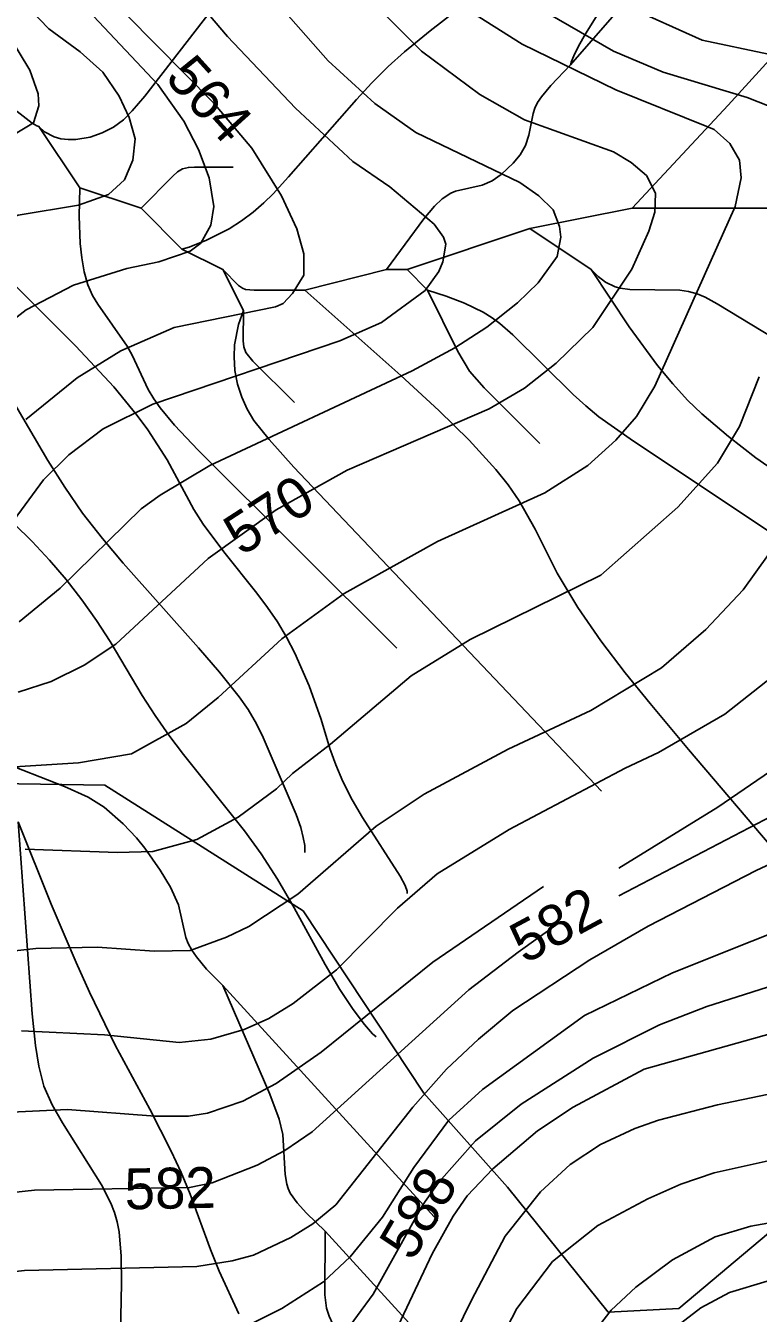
# Model space of a CAD drawing. Extents: x -709584 to -702006, y -1161789 to -1157496.
# Drawn here: x -709080.2 to -708901.1, y -1161487.1 to -1161172.4 of the extents above; entities that cross this region are included whole.
import ezdxf

# ---------------------------------------------------------------- set-up
doc = ezdxf.new("R2010")
doc.units = 0
for name, color, linetype in [('103_hranice KÚ', 7, 'Continuous'), ('120_vrstevnice hlavní', 7, 'Continuous'), ('121_vrstevnice hlavní_popis', 7, 'Continuous'), ('122_vrstevnice základní', 7, 'Continuous'), ('411_akumulovaný odtok', 7, 'Continuous')]:
    doc.layers.add(name, color=color, linetype=linetype)

msp = doc.modelspace()

# ---------------------------------------------------------------- linework, layer by layer
at = {"layer": '103_hranice KÚ'}
msp.add_lwpolyline([(-709234.65, -1161164.22), (-709251.02, -1161179.72), (-709249.63, -1161198), (-709213.45, -1161287.54), (-709205.25, -1161308.17), (-709193.08, -1161348.59), (-709153.37, -1161348.24), (-709123.88, -1161357.03), (-709060.82, -1161357.99), (-709012.33, -1161388.76), (-708982.87, -1161433.3), (-708962.39, -1161456.22), (-708937.82, -1161486.79), (-708920.55, -1161485.93), (-708896.6, -1161465.8)], dxfattribs=at)
at = {"layer": '120_vrstevnice hlavní'}
for points in [[(-709079.02, -1161168.53), (-709074.53, -1161173.16), (-709066.87, -1161178.8), (-709061.37, -1161183.72), (-709057.32, -1161189.65), (-709054.86, -1161194.85), (-709053.42, -1161200.06), (-709054, -1161205.27), (-709056.02, -1161210.04), (-709059.93, -1161213.66)], [(-708995.85, -1161166.21), (-708983.41, -1161178.65), (-708969.23, -1161189.21), (-708958.24, -1161195.43), (-708936.54, -1161203.24), (-708932.21, -1161205.84), (-708928.44, -1161209.03)], [(-708935.18, -1161378.26), (-708911.01, -1161363.35), (-708896.62, -1161353.53), (-708886.93, -1161345.57), (-708881, -1161339.21), (-708877.38, -1161334.43), (-708871.6, -1161323.59), (-708868.56, -1161315.49), (-708857.86, -1161273.54), (-708852.22, -1161258.79), (-708842.09, -1161239.11), (-708806.8, -1161180.1), (-708804.34, -1161173.73), (-708804.34, -1161170.26)], [(-708928.44, -1161209.03), (-708926.27, -1161213.37), (-708926.42, -1161218), (-708927.87, -1161222.62), (-708932.06, -1161231.88), (-708941.61, -1161246.2), (-708950.57, -1161254.88), (-708958.24, -1161260.96), (-708966.92, -1161266.02), (-709001.63, -1161281.06), (-709018.99, -1161290.75), (-709035.62, -1161302.61), (-709058.19, -1161323.59), (-709065.86, -1161328.65), (-709073.96, -1161332.7), (-709082.06, -1161335.3)], [(-709059.93, -1161213.66), (-709067.3, -1161216.26), (-709082.06, -1161218.72), (-709091.89, -1161222.48), (-709101.73, -1161228.55), (-709114.75, -1161240.56), (-709134.95, -1161267.22), (-709141, -1161271.45), (-709148.82, -1161275.61), (-709161.92, -1161277.32), (-709170.87, -1161279.18), (-709178.97, -1161282.22), (-709195.17, -1161290.46), (-709215.42, -1161296.68), (-709223.81, -1161292.05), (-709240.01, -1161287.14), (-709252.16, -1161285.4), (-709260.26, -1161285.11), (-709268.36, -1161285.69), (-709280.51, -1161287.86), (-709332.87, -1161304.06), (-709361.7, -1161310.62)], [(-709194.3, -1161457.09), (-709181.57, -1161463.02), (-709170.29, -1161466.21), (-709162.77, -1161467.07), (-709154.96, -1161466.93), (-709149.17, -1161466.06), (-709143.1, -1161462.73), (-709122.85, -1161447.55), (-709114.75, -1161443.06), (-709106.07, -1161440.03), (-709097.39, -1161438.58), (-709069.98, -1161437.27), (-709048.5, -1161438.87), (-709040.4, -1161438.87), (-709035.77, -1161438.14), (-709027.09, -1161435.25), (-709018.99, -1161430.91), (-709008, -1161423.25), (-708980.66, -1161401.26), (-708953.61, -1161382.78)], [(-708859.59, -1161407.91), (-708929.02, -1161427.44), (-708946.38, -1161436.7), (-708955.06, -1161442.48), (-708966.05, -1161451.74), (-708972.27, -1161458.39), (-708975.74, -1161463.31), (-708980.81, -1161472.57), (-708993.97, -1161500.34), (-708999.18, -1161509.6), (-709005.39, -1161518.57), (-709013.93, -1161527.53), (-709018.99, -1161531.58), (-709027.67, -1161535.49)]]:
    msp.add_lwpolyline(points, dxfattribs=at)
at = {"layer": '122_vrstevnice základní'}
for points in [[(-708697.59, -1161129.04), (-708733.32, -1161184.73), (-708743.59, -1161203.24), (-708750.96, -1161219.44), (-708758.78, -1161242.58), (-708764.27, -1161270.36), (-708767.89, -1161300.44), (-708768.03, -1161318.96), (-708767.17, -1161344.42), (-708767.45, -1161355.99), (-708769.19, -1161367.56), (-708771.5, -1161376.81), (-708775.84, -1161388.39), (-708781.92, -1161399.96), (-708786.98, -1161407.05), (-708793.2, -1161413.84), (-708802.75, -1161422.09), (-708812.73, -1161428.02), (-708839.05, -1161438.29), (-708853.23, -1161442.92), (-708867.4, -1161445.38), (-708895.75, -1161449.14), (-708911.95, -1161452.75), (-708920.06, -1161455.5)], [(-709036.06, -1161147.12), (-709006.26, -1161180.97)], [(-708759.21, -1161151.75), (-708797.11, -1161207.29), (-708816.06, -1161239.69), (-708824.01, -1161255.89), (-708832.26, -1161276.72), (-708849.32, -1161332.27), (-708852.65, -1161339.21), (-708858.29, -1161348.47), (-708863.64, -1161355.41), (-708869.57, -1161361.34), (-708878.11, -1161367.85), (-708901.69, -1161378.84), (-708928.01, -1161392.44), (-708942.33, -1161400.68), (-708961.13, -1161413.12), (-708969.52, -1161420.06), (-708977.33, -1161427.44), (-708985.58, -1161436.7)], [(-709034.9, -1161221.18), (-709034.18, -1161216.55), (-709035.34, -1161209.61), (-709037.94, -1161202.66), (-709041.56, -1161195.72), (-709047.92, -1161186.75), (-709078.01, -1161154.64)], [(-709061.23, -1161270.94), (-709049.08, -1161264.86), (-709003.37, -1161249.38), (-708993.25, -1161244.9), (-708982.54, -1161237.09), (-708979.21, -1161232.46), (-708978.2, -1161230.15), (-708977.48, -1161225.81), (-708978.06, -1161224.07), (-708980.37, -1161220.89), (-708991.22, -1161211.78), (-709000.19, -1161205.56), (-709014.22, -1161192.54), (-709030.85, -1161175.04), (-709046.18, -1161156.96)], [(-708935.18, -1161385.03), (-708897.78, -1161365.53), (-708888.52, -1161360.04), (-708879.84, -1161353.38), (-708871.74, -1161344.13), (-708863.93, -1161331.11), (-708855.69, -1161307.68), (-708851.06, -1161289.45), (-708841.95, -1161263.41), (-708836.31, -1161250.4), (-708831.1, -1161239.98), (-708815.91, -1161213.95), (-708802.6, -1161193.7), (-708788.28, -1161173.45), (-708779.32, -1161158.98)], [(-709085.53, -1161353.67), (-709067.3, -1161352.52), (-709054.29, -1161350.34), (-709040.98, -1161342.97), (-709033.17, -1161336.6), (-709017.55, -1161322.28), (-709002.36, -1161311.15), (-708979.56, -1161298.5), (-708953.32, -1161286.56), (-708942.76, -1161279.9), (-708935.96, -1161273.68), (-708930.9, -1161267.9), (-708926.42, -1161260.52), (-708906.75, -1161216.55), (-708905.3, -1161209.61), (-708905.73, -1161205.27), (-708908.05, -1161201.22), (-708911.9, -1161197.74), (-708913.69, -1161197.02), (-708935.96, -1161188.05), (-708958.82, -1161176.92), (-708979.36, -1161163.9)], [(-708955.35, -1161167.8), (-708936.54, -1161178.65), (-708924.39, -1161183.72)], [(-708898.65, -1161179.38), (-708914.85, -1161175.9), (-708933.36, -1161167.66)], [(-709055.44, -1161169.83), (-709034.32, -1161191.24), (-709024.92, -1161202.37), (-709017.69, -1161213.95), (-709013.93, -1161222.05), (-709012.19, -1161228.12), (-709012.19, -1161233.33), (-709014.94, -1161237.81), (-709017.26, -1161240.27), (-709019.14, -1161241.14), (-709043.87, -1161246.2), (-709056.89, -1161251.84), (-709067.59, -1161258.5), (-709080.18, -1161268.62)], [(-709084.37, -1161174.6), (-709079.16, -1161183.28), (-709077.14, -1161189.07), (-709076.99, -1161191.96), (-709078.3, -1161196.15), (-709087.55, -1161201.65)], [(-709006.26, -1161180.97), (-708994.83, -1161191.38), (-708984.85, -1161198.47), (-708959.4, -1161210.76), (-708954.77, -1161213.95), (-708951.3, -1161217.42), (-708949.71, -1161221.47), (-708949.42, -1161224.07), (-708950.29, -1161228.84), (-708954.91, -1161235.21), (-708959.98, -1161240.13), (-708967.5, -1161246.06), (-708975.31, -1161251.12), (-708985.72, -1161256.76), (-709035.19, -1161279.9), (-709047.34, -1161287.14), (-709051.97, -1161290.46), (-709071.79, -1161309.84), (-709081.77, -1161318.09)], [(-708924.39, -1161183.72), (-708903.85, -1161189.94), (-708895.75, -1161193.12)], [(-709257.08, -1161299), (-709243.77, -1161299.86), (-709237.69, -1161300.88), (-709229.59, -1161303.34), (-709215.42, -1161309.41), (-709210.07, -1161314.33), (-709207.61, -1161315.78), (-709205.58, -1161315.78), (-709198.35, -1161313.17), (-709193.14, -1161312.02), (-709168.55, -1161300.3), (-709139.91, -1161291.04), (-709127.33, -1161285.54), (-709116.48, -1161278.02), (-709097.53, -1161256.91), (-709090.88, -1161250.25), (-709080.03, -1161241.86), (-709068.46, -1161235.79), (-709055.44, -1161231.74), (-709047.63, -1161230.15), (-709039.96, -1161227.54), (-709037.36, -1161225.52), (-709034.9, -1161221.18)], [(-708900.96, -1161258.21), (-708905.73, -1161270.36), (-708911.09, -1161279.32), (-708920.78, -1161290.03), (-708939.58, -1161306.66), (-708971.55, -1161322.43), (-708986.01, -1161331.25), (-709005.68, -1161348.03), (-709014.94, -1161355.12), (-709018.85, -1161358.88), (-709028.25, -1161365.82), (-709038.37, -1161371.32), (-709049.08, -1161374.21), (-709057.76, -1161374.5), (-709080.32, -1161373.63)], [(-709256.79, -1161323.88), (-709246.66, -1161327.35), (-709236.54, -1161332.27), (-709230.46, -1161335.88), (-709221.35, -1161342.97), (-709210.5, -1161350.06), (-709203.27, -1161352.37), (-709197.19, -1161352.8), (-709189.96, -1161351.36), (-709185.75, -1161349.38), (-709184.32, -1161347.45), (-709179.98, -1161342.39), (-709171.3, -1161335.45), (-709164.5, -1161331.98), (-709131.23, -1161320.11), (-709102.6, -1161311.15), (-709093.48, -1161305.36), (-709087.84, -1161299.57), (-709075.84, -1161283.38), (-709069.62, -1161277.3), (-709061.23, -1161270.94)], [(-709087.26, -1161398.95), (-709077.72, -1161397.93), (-709062.67, -1161397.64), (-709048.81, -1161398.62), (-709039.99, -1161398.38), (-709031.14, -1161395.19), (-709025.65, -1161392.58), (-709013.64, -1161384.63), (-708994.55, -1161367.99), (-708982.83, -1161360.18), (-708962.29, -1161349.19), (-708942.04, -1161339.79), (-708924.83, -1161329.37), (-708913.98, -1161319.97), (-708904.87, -1161310.28), (-708898.65, -1161301.6)], [(-708896.62, -1161330.67), (-708909.35, -1161340.65), (-708925.55, -1161350.06), (-708933.65, -1161353.82), (-708962, -1161368.86), (-708979.65, -1161379.71), (-708989.34, -1161388.1), (-709004.24, -1161403.14), (-709014.8, -1161411.39), (-709020.73, -1161415), (-709026.8, -1161417.75), (-709034.9, -1161420.06), (-709042.71, -1161420.93), (-709060.94, -1161419.05), (-709081.19, -1161418.04)], [(-708883.32, -1161388.39), (-708922.08, -1161403.86), (-708943.63, -1161414.28), (-708968.51, -1161432.36), (-708976.76, -1161439.88), (-708985.29, -1161451.45), (-708992.96, -1161463.6), (-709000.91, -1161473.29), (-709007.42, -1161479.37), (-709017.55, -1161485.88), (-709025.93, -1161490.07), (-709040.69, -1161495.28), (-709050.23, -1161497.16), (-709062.09, -1161498.17)], [(-709176.94, -1161480.81), (-709162.77, -1161481.97), (-709151.49, -1161483.56), (-709146.86, -1161482.12), (-709130.66, -1161473.87), (-709117.06, -1161466.21), (-709101.44, -1161460.56), (-709091.02, -1161458.4), (-709078.01, -1161456.95), (-709040.11, -1161456.37), (-709034.61, -1161455.21), (-709023.62, -1161450.87), (-709016.82, -1161447.26), (-709010.17, -1161442.77), (-708971.84, -1161408.06), (-708959.83, -1161398.8), (-708949.47, -1161391.43)], [(-708876.66, -1161400.25), (-708913.69, -1161412.11), (-708925.26, -1161416.59), (-708941.46, -1161424.69), (-708959.11, -1161435.97), (-708970.25, -1161444.94), (-708979.21, -1161455.07), (-708983.12, -1161460.56), (-708995.27, -1161482.41), (-709002.94, -1161492.82), (-709007.56, -1161498.17), (-709013.21, -1161503.52), (-709020.73, -1161509.02)], [(-708989.05, -1161520.3), (-708971.26, -1161483.85), (-708963.01, -1161468.23), (-708954.33, -1161457.38), (-708947.1, -1161450.73), (-708939.73, -1161445.81), (-708931.34, -1161441.91), (-708925.55, -1161439.88), (-708911.09, -1161436.12), (-708888.81, -1161431.49)], [(-708985.58, -1161436.7), (-709004.38, -1161460.56), (-709010.02, -1161465.19), (-709015.38, -1161468.52), (-709024.49, -1161472.86), (-709029.7, -1161474.3), (-709038.37, -1161475.61), (-709080.46, -1161476.65), (-709093.82, -1161478.11), (-709107.04, -1161481.47), (-709117.35, -1161485.73), (-709138.9, -1161498.17), (-709148.59, -1161504.82), (-709156.4, -1161504.82), (-709179.84, -1161499.76), (-709192.85, -1161494.56), (-709198.06, -1161491.52), (-709210.5, -1161482.55), (-709219.32, -1161474.88), (-709251.58, -1161442.63), (-709258.52, -1161437.57)], [(-708920.06, -1161455.5), (-708928.16, -1161459.12), (-708940.31, -1161465.63), (-708951.44, -1161474.45), (-708960.12, -1161485.88), (-708963.74, -1161492.82)], [(-708945.95, -1161497.74), (-708937.12, -1161486.31), (-708931.05, -1161480.67), (-708922.08, -1161474.02), (-708911.67, -1161468.38), (-708902.99, -1161465.77), (-708891.42, -1161463.75)], [(-708898.94, -1161479.22), (-708908.19, -1161481.97), (-708915.14, -1161485.73), (-708924.07, -1161492.56)]]:
    msp.add_lwpolyline(points, dxfattribs=at)
at = {"layer": '411_akumulovaný odtok'}
for p, q in [((-709066.99, -1161212), (-709076.99, -1161197)), ((-709051.99, -1161217), (-709066.99, -1161212)), ((-709041.99, -1161227), (-709051.99, -1161217)), ((-708931.99, -1161217), (-708956.99, -1161222)), ((-708891.99, -1161217), (-708931.99, -1161217)), ((-708956.99, -1161222), (-708986.99, -1161232)), ((-708941.99, -1161232), (-708956.99, -1161222)), ((-709031.99, -1161232), (-709041.99, -1161227)), ((-709026.99, -1161242), (-709031.99, -1161232)), ((-708991.99, -1161232), (-709011.99, -1161237)), ((-708986.99, -1161232), (-708991.99, -1161232)), ((-708981.99, -1161237), (-708986.99, -1161232)), ((-708979.49, -1161464.5), (-709031.99, -1161407))]:
    msp.add_line(p, q, dxfattribs=at)
for points in [[(-708859.49, -1161049.5), (-708865.18, -1161058.29), (-708869.11, -1161064.76), (-708872.83, -1161071.51), (-708874.36, -1161074.69), (-708875.54, -1161077.59), (-708876.46, -1161080.43), (-708877.95, -1161086.24), (-708879.95, -1161095.03), (-708881.5, -1161100.77), (-708882.45, -1161103.56), (-708883.59, -1161106.26), (-708885.04, -1161108.98), (-708886.69, -1161111.61), (-708890.39, -1161116.68), (-708896.46, -1161124.04), (-708946.99, -1161182)], [(-708939.49, -1161134.5), (-708941.17, -1161137.34), (-708943.97, -1161141.34), (-708948.07, -1161146.25), (-708950.53, -1161148.81), (-708953.05, -1161151.23), (-708957.75, -1161155.29), (-708981.3, -1161173.64), (-708987.59, -1161178.79), (-708991.62, -1161182.39), (-708995.56, -1161186.33), (-708999.36, -1161190.43), (-709015.96, -1161209.35), (-709019.74, -1161213.49), (-709022.01, -1161215.69), (-709024.62, -1161217.94), (-709027.47, -1161220.11), (-709030.46, -1161222.05), (-709035.98, -1161224.85), (-709040.25, -1161226.5), (-709041.99, -1161227)], [(-709021.99, -1161152), (-709051.1, -1161189.61), (-709054.13, -1161193.22), (-709056.31, -1161195.4), (-709058.76, -1161197.18), (-709061.49, -1161198.55), (-709064.41, -1161199.61), (-709067.95, -1161200.2), (-709069.81, -1161200.22), (-709071.61, -1161200.02), (-709073.25, -1161199.58), (-709075.58, -1161198.34), (-709076.99, -1161197)], [(-709076.99, -1161197), (-709077.48, -1161196.87), (-709078.6, -1161196.19), (-709082.23, -1161193.38), (-709095.41, -1161180.8), (-709098.06, -1161178.67), (-709100.55, -1161177.08), (-709103.08, -1161175.76), (-709108.39, -1161173.49), (-709130.66, -1161165.63)], [(-708940.79, -1161170.25), (-708943.4, -1161174.4), (-708945.08, -1161177.39), (-708946.25, -1161179.76), (-708946.9, -1161181.35), (-708946.99, -1161182)], [(-708887.96, -1161168.93), (-708895.04, -1161177.1), (-708908.53, -1161191.86), (-708931.99, -1161217)], [(-708946.99, -1161182), (-708951.87, -1161186.98), (-708954.15, -1161189.79), (-708955.07, -1161191.2), (-708955.74, -1161192.55), (-708956.15, -1161193.83), (-708957.2, -1161199.14), (-708958, -1161201.68), (-708959.33, -1161203.95), (-708961.04, -1161206.03), (-708964.01, -1161208.8), (-708966.2, -1161210.31), (-708968.62, -1161211.34), (-708975.12, -1161212.84), (-708976.31, -1161213.32), (-708978.41, -1161214.71), (-708980.28, -1161216.51), (-708982.9, -1161219.62), (-708991.99, -1161232)], [(-709029.49, -1161207), (-709038.89, -1161206.94), (-709040.41, -1161207.03), (-709041.84, -1161207.36), (-709043.09, -1161208.14), (-709044.23, -1161209.17), (-709051.99, -1161217)], [(-709011.99, -1161374.5), (-709012, -1161372.72), (-709012.34, -1161370.8), (-709012.96, -1161368.37), (-709014.06, -1161365.16), (-709022.16, -1161346.39), (-709023.81, -1161343), (-709025.85, -1161339.54), (-709028.03, -1161336.43), (-709032.81, -1161330.36), (-709037.92, -1161324.42), (-709056.34, -1161303.76), (-709061.44, -1161297.73), (-709066.29, -1161291.51), (-709070.64, -1161285.18), (-709074.74, -1161278.66), (-709092.35, -1161248.74), (-709098.69, -1161238.6), (-709101.43, -1161234.75), (-709107.49, -1161227.19), (-709113.46, -1161220.58), (-709121.99, -1161212)], [(-708989.49, -1161324.5), (-709037.99, -1161276.17), (-709043.78, -1161270.01), (-709047.31, -1161265.77), (-709048.88, -1161263.57), (-709050.26, -1161261.29), (-709054.13, -1161252.89), (-709055.35, -1161250.74), (-709062.55, -1161240.47), (-709063.86, -1161238.31), (-709064.99, -1161235.72), (-709065.88, -1161232.58), (-709066.49, -1161229.16), (-709066.86, -1161225.63), (-709067.13, -1161218.96), (-709066.99, -1161212)], [(-708986.99, -1161384.5), (-708986.94, -1161383.91), (-708987.47, -1161382.5), (-708988.68, -1161380.23), (-708997.86, -1161365.92), (-709000.4, -1161361.58), (-709002.68, -1161357.14), (-709004.42, -1161353.03), (-709005.83, -1161349.07), (-709007.98, -1161341.99), (-709010.9, -1161333.77), (-709014.43, -1161325.75), (-709016.45, -1161321.87), (-709018.68, -1161318.11), (-709021.1, -1161314.56), (-709023.69, -1161311.11), (-709031.77, -1161301.02), (-709036.83, -1161294.19), (-709039.06, -1161290.65), (-709045.59, -1161278.54), (-709050.31, -1161271.19), (-709052.91, -1161267.63), (-709058.66, -1161260.69), (-709067.96, -1161250.7), (-709084.12, -1161234.51)], [(-709011.99, -1161237), (-709024.36, -1161237.04), (-709026.48, -1161236.84), (-709027.21, -1161236.55), (-709028.18, -1161235.86), (-709031.99, -1161232)], [(-708891.99, -1161252), (-708911.19, -1161240.37), (-708914.12, -1161238.78), (-708916.11, -1161237.9), (-708918.19, -1161237.33), (-708920.34, -1161237.06), (-708932.5, -1161236.89), (-708934.87, -1161236.57), (-708936.15, -1161236.2), (-708938.48, -1161235.05), (-708940.3, -1161233.68), (-708941.99, -1161232)], [(-708894.85, -1161282.78), (-708901.74, -1161278.03), (-708908.45, -1161272.83), (-708914.96, -1161267.24), (-708918.4, -1161263.88), (-708922, -1161259.94), (-708925.74, -1161255.42), (-708932.72, -1161245.99), (-708941.99, -1161232)], [(-708851.99, -1161427), (-708918.21, -1161349.27), (-708927.57, -1161338.09), (-708933.66, -1161330.55), (-708939.59, -1161322.73), (-708945.21, -1161314.6), (-708950.27, -1161306.19), (-708955.69, -1161295.46), (-708959.55, -1161288.52), (-708962.26, -1161284.6), (-708965.24, -1161280.85), (-708971.76, -1161273.69), (-708979.18, -1161266.45), (-708988.49, -1161257.9), (-709011.99, -1161237)], [(-708954.49, -1161274.5), (-708968.14, -1161260.92), (-708971.75, -1161256.84), (-708974.53, -1161252.04), (-708981.99, -1161237)], [(-708896.99, -1161297), (-708931.64, -1161273.97), (-708940.1, -1161267.97), (-708943.3, -1161265.34), (-708946.36, -1161262.54), (-708961.16, -1161247.97), (-708964.27, -1161245.2), (-708966.18, -1161243.8), (-708968.37, -1161242.43), (-708972.97, -1161240.18), (-708977.38, -1161238.48), (-708981.99, -1161237)], [(-708939.49, -1161359.5), (-709014.62, -1161280.26), (-709020.69, -1161273.54), (-709024.42, -1161268.9), (-709026.09, -1161266.12), (-709027.39, -1161263.17), (-709028.39, -1161259.97), (-709029.03, -1161256.66), (-709029.26, -1161253.36), (-709029.11, -1161250.4), (-709028.18, -1161245.39), (-709026.99, -1161242)], [(-709014.49, -1161264.5), (-709024.7, -1161254.37), (-709026.39, -1161252.31), (-709026.9, -1161250.91), (-709027.05, -1161249.4), (-709026.99, -1161242)], [(-708994.49, -1161419.5), (-708995.41, -1161418.8), (-708997.39, -1161416.5), (-709000.14, -1161412.8), (-709003.39, -1161407.92), (-709006.97, -1161401.86), (-709014.56, -1161388), (-709018.63, -1161381), (-709022.67, -1161374.77), (-709026.68, -1161369.2), (-709041.62, -1161350.53), (-709045.19, -1161345.81), (-709048.55, -1161341.02), (-709051.73, -1161336.13), (-709059.52, -1161322.9), (-709062.86, -1161317.73), (-709066.47, -1161312.69), (-709070.32, -1161307.78), (-709074.37, -1161303.02), (-709078.63, -1161298.43), (-709082.98, -1161294.12)], [(-709031.99, -1161407), (-709035.96, -1161403), (-709038.45, -1161399.97), (-709039.56, -1161398.34), (-709040.45, -1161396.7), (-709041.03, -1161395.25), (-709042.86, -1161387.24), (-709044.83, -1161382.91), (-709047.34, -1161378.75), (-709051.1, -1161373.39), (-709053.12, -1161370.91), (-709056.35, -1161367.5), (-709061.01, -1161363.38), (-709064.95, -1161360.91), (-709070.69, -1161358.32), (-709086.99, -1161352)], [(-709056.99, -1161492), (-709056.76, -1161479.69), (-709056.88, -1161473.11), (-709057.37, -1161467.18), (-709057.82, -1161464.76), (-709058.46, -1161462.46), (-709059.35, -1161460.15), (-709061.64, -1161455.69), (-709071.2, -1161440.56), (-709073.69, -1161436.14), (-709075.71, -1161431.57), (-709077.01, -1161426.68), (-709077.82, -1161421.62), (-709078.6, -1161413.88), (-709081.99, -1161367)], [(-709028.1, -1161487.21), (-709032.86, -1161476.77), (-709035.04, -1161471.46), (-709039.96, -1161457.94), (-709042.16, -1161452.69), (-709044.59, -1161447.49), (-709049.88, -1161437.18), (-709058.28, -1161421.58), (-709064.61, -1161408.57), (-709067.85, -1161401.35), (-709073.92, -1161387.09), (-709081.99, -1161367)], [(-709006.99, -1161467), (-709011.57, -1161462.6), (-709013.81, -1161460.12), (-709015.52, -1161457.72), (-709016.02, -1161456.62), (-709016.36, -1161455.52), (-709016.74, -1161453.18), (-709017.36, -1161443.35), (-709018.22, -1161439.64), (-709020.55, -1161433.55), (-709031.99, -1161407)], [(-708986.99, -1161517), (-709002.83, -1161493.4), (-709005.11, -1161489.71), (-709006.05, -1161487.81), (-709006.67, -1161485.8), (-709007.06, -1161482.58), (-709006.99, -1161467)], [(-708924.49, -1161544.5), (-708930.27, -1161538.92), (-708934.63, -1161535.33), (-708936.96, -1161533.69), (-708941.55, -1161531.07), (-708949.51, -1161527.2), (-708953.14, -1161524.76), (-708956.47, -1161521.85), (-708964.27, -1161513.77), (-709006.99, -1161467)]]:
    msp.add_lwpolyline(points, dxfattribs=at)

# ---------------------------------------------------------------- texts
at = {"layer": '121_vrstevnice hlavní_popis'}
for s, rotation, p in [('564', 312.1416, (-709046.4, -1161185.35)), ('570', 32.8962, (-709027.43, -1161302.17)), ('582', 28.2019, (-708958.22, -1161401.8)), ('582', 1.1316, (-709055.93, -1161461.72)), ('588', 59.4266, (-708985.64, -1161474.65))]:
    msp.add_text(s, height=10, rotation=rotation, dxfattribs=at).set_placement(p)

doc.saveas('drawing.dxf')
